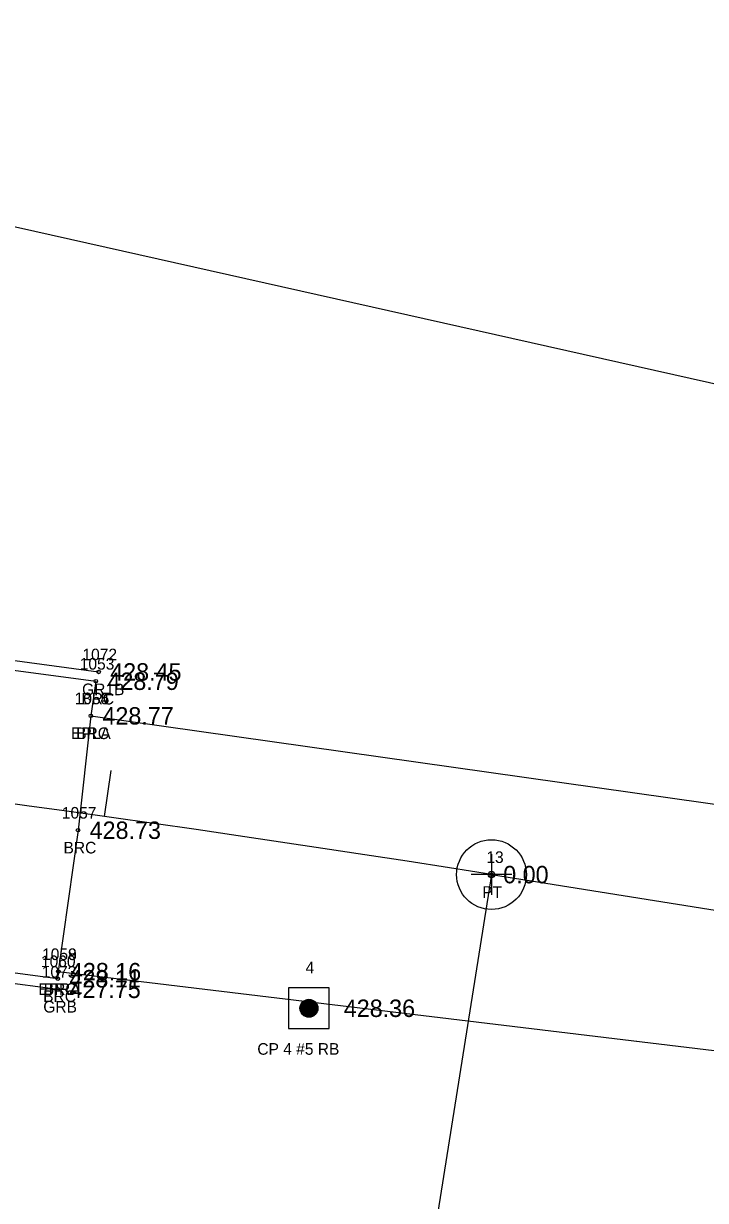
# Model space of a CAD drawing. Extents: x 1611114 to 1617038, y 769445 to 772083.
# Drawn here: x 1613960.4 to 1614019.1, y 771305 to 771406.3 of the extents above; entities that cross this region are included whole.
import ezdxf

# ---------------------------------------------------------------- set-up
doc = ezdxf.new("R2010")
doc.units = 0
for name, color, linetype in [('Default', 7, 'Continuous'), ('RD_EX_Bridge', 7, 'Continuous'), ('RD_EX_Bridge_txCode', 7, 'Continuous'), ('RD_EX_GuardRail', 7, 'Continuous'), ('RD_EX_GuardRail_txCode', 7, 'Continuous'), ('RD_EX_Road', 7, 'Continuous'), ('RD_EX_Road_txCode', 7, 'Continuous'), ('RD_EX_TX_Bridge_ELEV', 7, 'Continuous'), ('RD_EX_TX_GuardRail_ELEV', 7, 'Continuous'), ('RD_EX_TX_Road_ELEV', 7, 'Continuous'), ('RD_EX_VEG', 7, 'Continuous'), ('RD_HC_Cl', 7, 'Continuous'), ('RD_HC_Data', 7, 'Continuous'), ('RD_HC_Data_Tic', 7, 'Continuous'), ('RD_HC_Survey', 7, 'Continuous'), ('RD_HC_Survey_ELEV', 7, 'Continuous'), ('RD_HC_Survey_txCode', 7, 'Continuous'), ('RD_HC_txCode', 7, 'Continuous'), ('RD_SMD_Locator', 7, 'Continuous')]:
    doc.layers.add(name, color=color, linetype=linetype)

msp = doc.modelspace()

# ---------------------------------------------------------------- linework, layer by layer
at = {"layer": 'Default'}
for p, q in [((1614000.69, 771334.81), (1614000.69, 771331.31)), ((1614002.44, 771333.06), (1613998.94, 771333.06)), ((1614000.69, 771333.06), (1615062.36, 771164.28))]:
    msp.add_line(p, q, dxfattribs=at)
msp.add_arc((1613700.84, 769446.93), 1909.82, 80.96676, 95.06271, dxfattribs=at)
msp.add_arc((1613700.84, 769446.93), 1909.82, 80.96676, 95.06271, dxfattribs=at)
at = {"layer": 'RD_EX_Bridge'}
msp.add_lwpolyline([(1613889.09, 771333.98), (1613889.25, 771335.84), (1613890.87, 771346.48), (1613892.3, 771358.63), (1613892.48, 771359.61), (1613966.64, 771349.7), (1613966.21, 771346.72), (1613965.11, 771336.88), (1613963.41, 771324.71), (1613963.37, 771324.1), (1613889.09, 771333.98)], dxfattribs=at)
at = {"layer": 'RD_EX_GuardRail'}
for p, q in [((1613892.36, 771360.53), (1613966.88, 771350.5)), ((1613888.77, 771333.18), (1613963.37, 771323.19))]:
    msp.add_line(p, q, dxfattribs=at)
at = {"layer": 'RD_EX_Road'}
for points in [[(1613966.21, 771346.72), (1614065.91, 771332.61), (1614166, 771316.74), (1614252.8, 771303.53), (1614264.27, 771301.76), (1614271.95, 771300.8), (1614363.43, 771285.99), (1614463.49, 771269.68), (1614562.24, 771253.72), (1614661.91, 771238.32)], [(1613963.41, 771324.71), (1614062.98, 771312.73), (1614162.48, 771297.04), (1614260.87, 771281.9), (1614360.23, 771265.95), (1614460.24, 771249.77), (1614559.17, 771233.87), (1614658.84, 771218.34)]]:
    msp.add_lwpolyline(points, dxfattribs=at)
at = {"layer": 'RD_EX_VEG'}
msp.add_lwpolyline([(1613190.16, 771350.86), (1613289.21, 771359.12), (1613387.94, 771369.51), (1613489.82, 771379.95), (1613503.78, 771396.75), (1613539.01, 771398.99), (1613588.71, 771402.91), (1613642.02, 771405.83), (1613690.35, 771406.29), (1613743.43, 771406.09), (1613794.76, 771402.87), (1613849.1, 771400.75), (1613898.57, 771402.5), (1614071.38, 771363.76), (1614171, 771346.54), (1614270.56, 771328.42), (1614365.98, 771308.81), (1614467.36, 771290.78), (1614565.75, 771274.12), (1614666.78, 771259.85)], dxfattribs=at)
at = {"layer": 'RD_HC_Cl'}
msp.add_line((1614000.69, 771333.06), (1615062.36, 771164.28), dxfattribs=at)
msp.add_arc((1613700.84, 769446.93), 1909.82, 80.96676, 95.06271, dxfattribs=at)
at = {"layer": 'RD_HC_Data'}
msp.add_line((1614000.69, 771333.06), (1613981.8, 771214.19), dxfattribs=at)
for radius in [3, 0.282]:
    msp.add_circle((1614000.69, 771333.06), radius, dxfattribs=at)
at = {"layer": 'RD_HC_Data_Tic'}
msp.add_line((1613967.4, 771338.06), (1613967.96, 771342.02), dxfattribs=at)
at = {"layer": 'RD_HC_Survey'}
for p, q in [((1613984.25, 771321.3), (1613984.25, 771321.82)), ((1613984.28, 771321.24), (1613984.28, 771321.88)), ((1613984.3, 771321.19), (1613984.3, 771321.93)), ((1613984.33, 771321.15), (1613984.33, 771321.97)), ((1613984.35, 771321.11), (1613984.35, 771322.01)), ((1613984.38, 771321.08), (1613984.38, 771322.04)), ((1613984.4, 771321.05), (1613984.4, 771322.07)), ((1613984.43, 771321.02), (1613984.43, 771322.1)), ((1613984.45, 771321), (1613984.45, 771322.12)), ((1613984.48, 771320.97), (1613984.48, 771322.14)), ((1613984.5, 771320.95), (1613984.5, 771322.16)), ((1613984.53, 771320.94), (1613984.53, 771322.18)), ((1613984.55, 771320.92), (1613984.55, 771322.2)), ((1613984.58, 771320.9), (1613984.58, 771322.22)), ((1613984.6, 771320.89), (1613984.6, 771322.23)), ((1613984.62, 771320.87), (1613984.62, 771322.24)), ((1613984.65, 771320.86), (1613984.65, 771322.26)), ((1613984.67, 771320.85), (1613984.67, 771322.27)), ((1613984.7, 771320.84), (1613984.7, 771322.28)), ((1613984.72, 771320.83), (1613984.72, 771322.29)), ((1613984.75, 771320.82), (1613984.75, 771322.29)), ((1613984.77, 771320.82), (1613984.77, 771322.3)), ((1613984.8, 771320.81), (1613984.8, 771322.31)), ((1613984.82, 771320.8), (1613984.82, 771322.31)), ((1613984.85, 771320.8), (1613984.85, 771322.32)), ((1613984.87, 771320.8), (1613984.87, 771322.32)), ((1613984.9, 771320.79), (1613984.9, 771322.32)), ((1613984.92, 771320.79), (1613984.92, 771322.33)), ((1613984.95, 771320.79), (1613984.95, 771322.33)), ((1613984.97, 771320.79), (1613984.97, 771322.33)), ((1613985, 771320.79), (1613985, 771322.33)), ((1613985.02, 771320.79), (1613985.02, 771322.33)), ((1613985.05, 771320.79), (1613985.05, 771322.33)), ((1613985.07, 771320.79), (1613985.07, 771322.32)), ((1613985.1, 771320.8), (1613985.1, 771322.32)), ((1613985.12, 771320.8), (1613985.12, 771322.31)), ((1613985.14, 771320.81), (1613985.14, 771322.31)), ((1613985.17, 771320.81), (1613985.17, 771322.3)), ((1613985.19, 771320.82), (1613985.19, 771322.3)), ((1613985.22, 771320.83), (1613985.22, 771322.29)), ((1613985.24, 771320.84), (1613985.24, 771322.28)), ((1613985.27, 771320.85), (1613985.27, 771322.27)), ((1613985.29, 771320.86), (1613985.29, 771322.26)), ((1613985.32, 771320.87), (1613985.32, 771322.25)), ((1613985.34, 771320.88), (1613985.34, 771322.24)), ((1613985.37, 771320.9), (1613985.37, 771322.22)), ((1613985.39, 771320.91), (1613985.39, 771322.21)), ((1613985.42, 771320.93), (1613985.42, 771322.19)), ((1613985.44, 771320.95), (1613985.44, 771322.17)), ((1613985.47, 771320.96), (1613985.47, 771322.15)), ((1613985.49, 771320.99), (1613985.49, 771322.13)), ((1613985.52, 771321.01), (1613985.52, 771322.11)), ((1613985.54, 771321.03), (1613985.54, 771322.08)), ((1613985.57, 771321.06), (1613985.57, 771322.06)), ((1613985.59, 771321.09), (1613985.59, 771322.02)), ((1613985.61, 771321.13), (1613985.61, 771321.99)), ((1613985.64, 771321.17), (1613985.64, 771321.95)), ((1613985.66, 771321.21), (1613985.66, 771321.91)), ((1613985.69, 771321.27), (1613985.69, 771321.85)), ((1613985.71, 771321.34), (1613985.71, 771321.78)), ((1613984.23, 771321.38), (1613984.23, 771321.74)), ((1613985.74, 771321.45), (1613985.74, 771321.67))]:
    msp.add_line(p, q, dxfattribs=at)
msp.add_lwpolyline([(1613986.73, 771323.31), (1613983.23, 771323.31), (1613983.23, 771319.81), (1613986.73, 771319.81)], close=True, dxfattribs=at)
msp.add_circle((1613984.98, 771321.56), 0.769, dxfattribs=at)
at = {"layer": 'RD_SMD_Locator'}
for centre in [(1613966.88, 771350.5), (1613966.64, 771349.7), (1613966.21, 771346.72), (1613966.21, 771346.72), (1613965.11, 771336.88), (1614000.69, 771333.06), (1613963.41, 771324.71), (1613963.41, 771324.71), (1613963.37, 771324.1), (1613963.37, 771323.19), (1613984.98, 771321.56)]:
    msp.add_circle(centre, 0.15, dxfattribs=at)

# ---------------------------------------------------------------- texts
at = {"layer": 'RD_EX_Bridge_txCode'}
for s, p in [('1053', (1613965.26, 771350.7)), ('1054', (1613964.82, 771347.72)), ('BRC', (1613965.39, 771347.7)), ('BRC', (1613964.95, 771344.72)), ('1057', (1613963.72, 771337.88)), ('BRC', (1613963.86, 771334.88)), ('1060', (1613961.92, 771325.1)), ('1059', (1613962.02, 771325.71)), ('BRC', (1613962.11, 771322.1)), ('BRC', (1613962.16, 771322.71))]:
    msp.add_text(s, height=1, dxfattribs=at).set_placement(p)
at = {"layer": 'RD_EX_GuardRail_txCode'}
for s, p in [('1072', (1613965.49, 771351.5)), ('GR1B', (1613965.46, 771348.5)), ('1073', (1613961.99, 771324.19)), ('GRB', (1613962.12, 771321.19))]:
    msp.add_text(s, height=1, dxfattribs=at).set_placement(p)
at = {"layer": 'RD_EX_Road_txCode'}
for s, p in [('1055', (1613964.82, 771347.72)), ('EPLA', (1613964.51, 771344.72)), ('1058', (1613962.02, 771325.71)), ('EPRA', (1613961.69, 771322.71))]:
    msp.add_text(s, height=1, dxfattribs=at).set_placement(p)
at = {"layer": 'RD_EX_TX_Bridge_ELEV'}
for s, p in [('428.79', (1613967.64, 771348.95)), ('428.77', (1613967.21, 771345.97)), ('428.73', (1613966.11, 771336.13)), ('428.11', (1613964.37, 771323.35)), ('428.16', (1613964.41, 771323.96))]:
    msp.add_text(s, height=1.5, dxfattribs=at).set_placement(p)
at = {"layer": 'RD_EX_TX_GuardRail_ELEV'}
for s, p in [('428.45', (1613967.88, 771349.75)), ('427.75', (1613964.37, 771322.44))]:
    msp.add_text(s, height=1.5, dxfattribs=at).set_placement(p)
at = {"layer": 'RD_EX_TX_Road_ELEV'}
for s, p in [('428.77', (1613967.21, 771345.97)), ('428.16', (1613964.41, 771323.96))]:
    msp.add_text(s, height=1.5, dxfattribs=at).set_placement(p)
at = {"layer": 'RD_HC_Survey_ELEV'}
for s, p in [('0.00', (1614001.7, 771332.31)), ('428.36', (1613987.98, 771320.81))]:
    msp.add_text(s, height=1.5, dxfattribs=at).set_placement(p)
at = {"layer": 'RD_HC_Survey_txCode'}
for s, p in [('4', (1613984.69, 771324.56)), ('CP 4 #5 RB', (1613980.54, 771317.56))]:
    msp.add_text(s, height=1, dxfattribs=at).set_placement(p)
at = {"layer": 'RD_HC_txCode'}
for s, p in [('13', (1614000.25, 771334.06)), ('PT', (1613999.9, 771331.06))]:
    msp.add_text(s, height=1, dxfattribs=at).set_placement(p)

doc.saveas('drawing.dxf')
